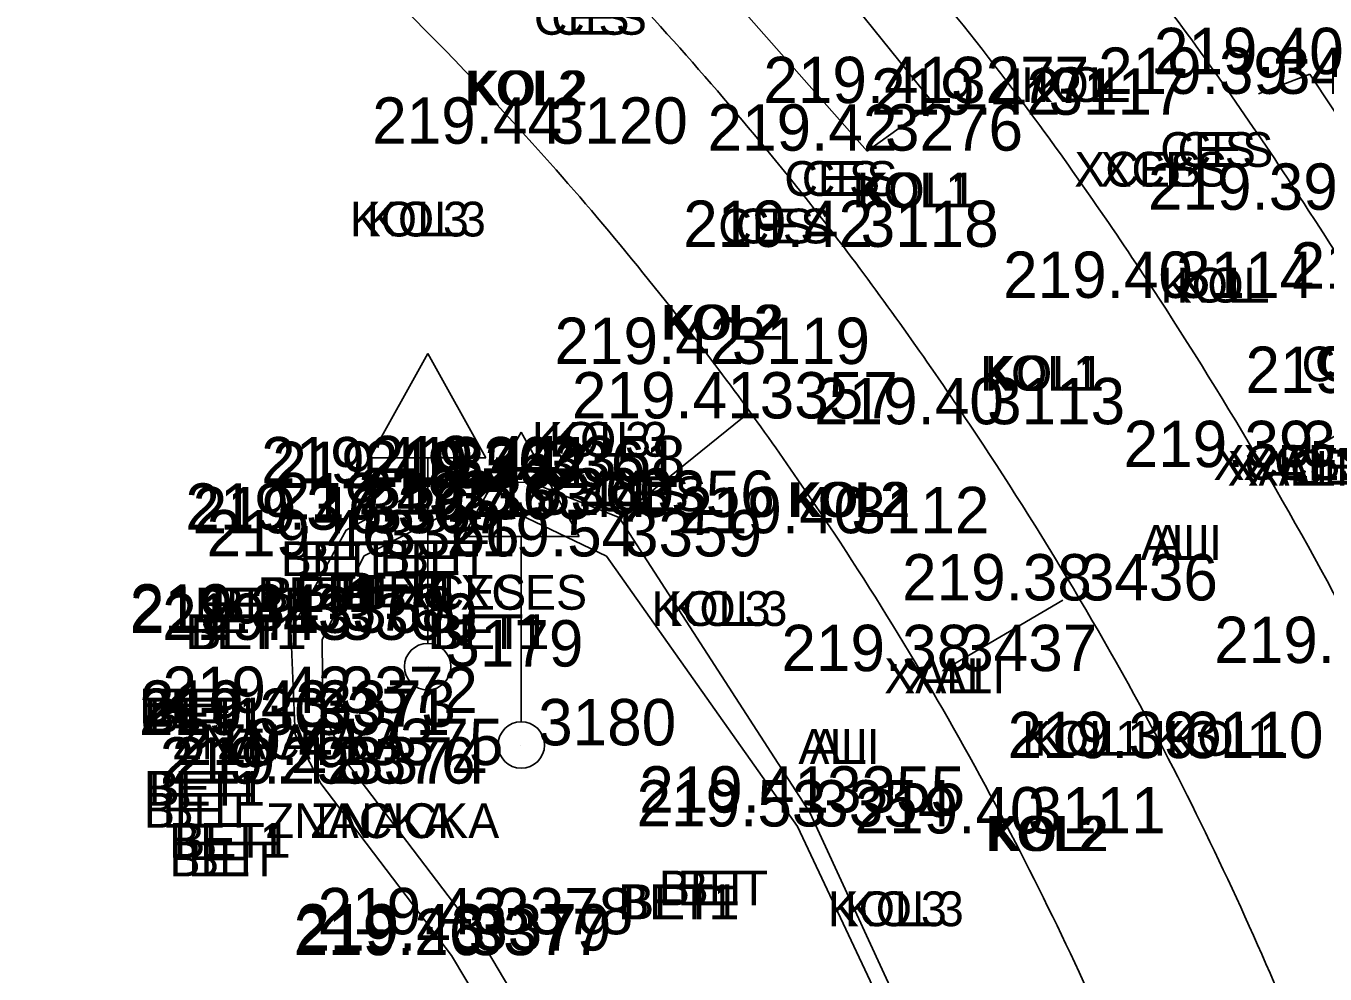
# Model space of a CAD drawing. Extents: x -471047 to -470889, y -1102859 to -1102000.
# Drawn here: x -470937.81 to -470926.61, y -1102024.77 to -1102016.59 of the extents above; entities that cross this region are included whole.
import ezdxf

# ---------------------------------------------------------------- set-up
doc = ezdxf.new("R2010")
doc.units = 0
for name, color, linetype in [('Vrstva 1', 7, 'Continuous'), ('Vrstva 19', 7, 'Continuous'), ('Vrstva 29', 7, 'Continuous'), ('Vrstva 34', 7, 'Continuous'), ('Vrstva 35', 7, 'Continuous'), ('Vrstva 36', 7, 'Continuous'), ('Vrstva 38', 7, 'Continuous'), ('Vrstva 7', 7, 'Continuous'), ('Vrstva 8', 7, 'Continuous')]:
    doc.layers.add(name, color=color, linetype=linetype)

msp = doc.modelspace()

# ---------------------------------------------------------------- linework, layer by layer
at = {"layer": 'Vrstva 1'}
for points in [[(-471040.344, -1102858.385), (-471031.676, -1102846.187), (-471026.357, -1102838.629), (-471023.212, -1102833.975), (-471019.21, -1102827.465), (-471016.861, -1102823.272), (-471013.099, -1102815.912), (-471010.824, -1102810.955), (-471007.329, -1102802.292), (-471005.34, -1102796.515), (-471002.842, -1102787.838), (-471001.3, -1102780.997), (-471000.19, -1102774.713), (-470999.247, -1102768.204), (-470998.794, -1102764.784), (-470997.199, -1102751.812), (-470994.899, -1102732.807), (-470992.551, -1102713.262), (-470990.326, -1102694.887), (-470988.122, -1102676.57), (-470985.812, -1102657.305), (-470983.537, -1102638.407), (-470981.386, -1102620.622), (-470979.843, -1102608.014), (-470976.377, -1102579.253), (-470972.945, -1102550.69), (-470970.475, -1102530.206), (-470967.905, -1102508.801), (-470965.053, -1102485.131), (-470962.734, -1102465.9), (-470960.173, -1102444.812), (-470957.795, -1102425.103), (-470954.965, -1102401.839), (-470953.834, -1102392.574), (-470952.33, -1102379.985), (-470950.744, -1102366.853), (-470948.978, -1102352.106), (-470947.037, -1102335.844), (-470944.949, -1102318.462), (-470944.013, -1102310.745), (-470942.39, -1102297.267), (-470939.519, -1102273.45), (-470937.593, -1102257.43), (-470936.064, -1102244.81), (-470934.114, -1102228.634), (-470931.621, -1102207.856), (-470929.536, -1102190.857), (-470926.572, -1102166.31), (-470924.91, -1102152.663), (-470923.413, -1102140.333), (-470921.923, -1102127.669), (-470921.155, -1102120.084), (-470920.446, -1102109.574), (-470919.912, -1102099.137), (-470919.63, -1102088.981), (-470919.523, -1102081.193), (-470919.563, -1102070.395), (-470919.714, -1102064.236), (-470920.134, -1102054.704), (-470920.462, -1102047.615), (-470920.599, -1102044.52), (-470920.743, -1102041.873), (-470921.125, -1102034.455), (-470921.774, -1102030.337), (-470922.418, -1102027.787), (-470923.734, -1102023.93), (-470924.872, -1102021.434), (-470926.752, -1102018.182), (-470927.953, -1102016.45), (-470929.616, -1102014.424), (-470932.252, -1102011.756), (-470935.111, -1102009.425), (-470938.391, -1102007.371), (-470942.651, -1102005.401)], [(-471041.328, -1102857.18), (-471032.144, -1102844.242), (-471027.583, -1102837.763), (-471024.388, -1102833.028), (-471020.451, -1102826.6), (-471018.089, -1102822.378), (-471014.542, -1102815.445), (-471012.233, -1102810.418), (-471009.247, -1102803.108), (-471006.795, -1102796.098), (-471004.315, -1102787.532), (-471002.782, -1102780.723), (-471001.674, -1102774.458), (-471000.75, -1102768.095), (-471000.28, -1102764.601), (-470998.692, -1102751.741), (-470996.378, -1102732.635), (-470994.028, -1102713.058), (-470991.808, -1102694.749), (-470989.616, -1102676.447), (-470987.284, -1102657.013), (-470985.031, -1102638.272), (-470982.87, -1102620.431), (-470981.334, -1102607.933), (-470977.881, -1102579.263), (-470974.429, -1102550.492), (-470971.964, -1102530.054), (-470969.391, -1102508.607), (-470966.54, -1102484.984), (-470964.231, -1102465.853), (-470961.679, -1102444.752), (-470959.304, -1102425.078), (-470956.455, -1102401.634), (-470955.339, -1102392.489), (-470953.812, -1102379.71), (-470952.249, -1102366.808), (-470950.479, -1102352.023), (-470948.536, -1102335.868), (-470946.426, -1102318.233), (-470945.493, -1102310.531), (-470943.864, -1102297.013), (-470940.984, -1102273.071), (-470939.078, -1102257.195), (-470937.559, -1102244.684), (-470935.592, -1102228.353), (-470933.101, -1102207.653), (-470931.011, -1102190.57), (-470928.046, -1102166.021), (-470926.409, -1102152.578), (-470924.898, -1102140.121), (-470923.427, -1102127.544), (-470922.647, -1102119.826), (-470921.919, -1102109.229), (-470921.42, -1102099.134), (-470921.127, -1102089.016), (-470921.023, -1102081.453), (-470921.061, -1102070.468), (-470921.209, -1102064.314), (-470921.666, -1102053.966), (-470922.156, -1102043.345), (-470922.299, -1102039.934), (-470922.637, -1102034.36), (-470923.091, -1102031.241), (-470923.847, -1102028.247), (-470925.083, -1102024.594), (-470926.222, -1102022.086), (-470928.04, -1102018.943), (-470929.138, -1102017.357), (-470930.929, -1102015.175), (-470933.062, -1102013.049), (-470936.379, -1102010.368), (-470939.169, -1102008.662), (-470942.899, -1102006.906), (-470945.661, -1102005.908)], [(-471043.557, -1102855.955), (-471035.129, -1102844.026), (-471029.872, -1102836.499), (-471026.577, -1102831.578), (-471022.675, -1102825.415), (-471020.123, -1102821.053), (-471016.667, -1102814.59), (-471014.208, -1102809.45), (-471011.177, -1102802.451), (-471008.55, -1102795.333), (-471006.082, -1102787.209), (-471004.464, -1102780.376), (-471003.265, -1102774.167), (-471002.327, -1102767.948), (-471001.636, -1102762.527), (-471000.297, -1102751.605), (-470997.959, -1102732.524), (-470995.602, -1102712.802), (-470993.412, -1102694.623), (-470991.21, -1102676.17), (-470988.891, -1102656.857), (-470986.625, -1102638.083), (-470984.455, -1102620.195), (-470982.936, -1102607.733), (-470979.497, -1102579.223), (-470976.023, -1102550.279), (-470973.554, -1102529.822), (-470970.991, -1102508.497), (-470968.146, -1102484.787), (-470965.835, -1102465.72), (-470963.284, -1102444.529), (-470960.91, -1102424.942), (-470958.043, -1102401.343), (-470956.946, -1102392.356), (-470955.396, -1102379.408), (-470953.851, -1102366.636), (-470952.049, -1102351.733), (-470950.124, -1102335.611), (-470948.034, -1102318.083), (-470947.094, -1102310.328), (-470945.421, -1102296.51), (-470942.58, -1102272.848), (-470940.675, -1102256.948), (-470939.176, -1102244.526), (-470937.187, -1102228.174), (-470934.708, -1102207.467), (-470932.621, -1102190.433), (-470929.634, -1102165.778), (-470928.004, -1102152.415), (-470926.45, -1102139.595), (-470925.003, -1102127.418), (-470924.249, -1102119.695), (-470923.515, -1102109.093), (-470923.018, -1102099.069), (-470922.711, -1102088.911), (-470922.643, -1102081.356), (-470922.797, -1102070.414), (-470923.018, -1102064.454), (-470923.52, -1102053.203), (-470923.823, -1102047.529), (-470924.123, -1102041.506), (-470924.462, -1102037.486), (-470924.934, -1102031.904), (-470925.664, -1102028.672), (-470926.771, -1102025.506), (-470927.959, -1102022.914), (-470929.674, -1102020.028), (-470930.76, -1102018.498), (-470932.447, -1102016.478), (-470935.215, -1102013.816), (-470937.644, -1102011.98), (-470940.381, -1102010.371), (-470943.968, -1102008.669), (-470947.145, -1102007.524), (-470950.874, -1102006.74)], [(-471044.756, -1102855.056), (-471036.376, -1102843.177), (-471031.167, -1102835.741), (-471027.859, -1102830.8), (-471023.934, -1102824.593), (-471021.43, -1102820.312), (-471018.011, -1102813.91), (-471015.536, -1102808.75), (-471012.578, -1102801.897), (-471009.95, -1102794.77), (-471007.561, -1102786.914), (-471005.936, -1102780.074), (-471004.727, -1102773.818), (-471003.828, -1102767.827), (-471003.121, -1102762.345), (-471001.787, -1102751.467), (-470999.446, -1102732.348), (-470997.073, -1102712.539), (-470994.902, -1102694.521), (-470992.696, -1102676.023), (-470990.376, -1102656.68), (-470988.131, -1102638.071), (-470985.947, -1102620.018), (-470984.417, -1102607.512), (-470980.993, -1102579.08), (-470977.514, -1102550.137), (-470975.048, -1102529.649), (-470972.488, -1102508.37), (-470969.618, -1102484.508), (-470967.34, -1102465.669), (-470964.767, -1102444.39), (-470962.402, -1102424.781), (-470959.534, -1102401.193), (-470958.432, -1102392.151), (-470956.883, -1102379.208), (-470955.335, -1102366.424), (-470953.535, -1102351.506), (-470951.606, -1102335.399), (-470949.519, -1102317.94), (-470948.575, -1102310.159), (-470946.889, -1102296.144), (-470944.056, -1102272.618), (-470942.139, -1102256.659), (-470940.657, -1102244.341), (-470938.638, -1102227.749), (-470936.19, -1102207.298), (-470934.102, -1102190.255), (-470931.124, -1102165.639), (-470929.492, -1102152.254), (-470927.915, -1102139.252), (-470926.46, -1102127.103), (-470925.74, -1102119.604), (-470925.012, -1102108.913), (-470924.523, -1102099.054), (-470924.217, -1102088.866), (-470924.148, -1102081.334), (-470924.301, -1102070.391), (-470924.518, -1102064.43), (-470924.97, -1102054.435), (-470925.588, -1102041.569), (-470925.963, -1102035.313), (-470926.405, -1102032.225), (-470927.078, -1102029.198), (-470928.123, -1102026.148), (-470929.318, -1102023.558), (-470930.84, -1102020.97), (-470931.868, -1102019.515), (-470933.443, -1102017.605), (-470936.26, -1102014.885), (-470938.429, -1102013.255), (-470941.213, -1102011.639), (-470944.847, -1102009.927), (-470947.723, -1102008.912), (-470951.444, -1102008.161), (-470954.511, -1102007.931), (-470957.895, -1102008.041)]]:
    msp.add_spline(points, degree=3, dxfattribs=at)
at = {"layer": 'Vrstva 19'}
for p, q in [((-470934.344, -1102019.421), (-470934.844, -1102020.321)), ((-470934.344, -1102019.421), (-470933.844, -1102020.321)), ((-470933.537, -1102020.097), (-470934.037, -1102020.997)), ((-470933.537, -1102020.097), (-470933.037, -1102020.997)), ((-470933.844, -1102020.321), (-470934.844, -1102020.321)), ((-470934.344, -1102020.321), (-470934.344, -1102021.921)), ((-470933.037, -1102020.997), (-470934.037, -1102020.997)), ((-470933.537, -1102020.997), (-470933.537, -1102022.597))]:
    msp.add_line(p, q, dxfattribs=at)
for centre in [(-470934.344, -1102022.121), (-470933.537, -1102022.797)]:
    msp.add_circle(centre, 0.2, dxfattribs=at)
at = {"layer": 'Vrstva 29'}
for p, q in [((-470925.914, -1102019.764), (-470926.962, -1102020.396)), ((-470928.867, -1102021.548), (-470929.907, -1102022.157))]:
    msp.add_line(p, q, dxfattribs=at)
at = {"layer": 'Vrstva 34'}
for p, q in [((-470926.74, -1102017.01), (-470926.74, -1102017.01)), ((-470927.18, -1102017.18), (-470927.18, -1102017.18)), ((-470929.98, -1102017.26), (-470929.98, -1102017.26)), ((-470929.14, -1102017.36), (-470929.14, -1102017.36)), ((-470933.44, -1102017.61), (-470933.44, -1102017.61)), ((-470930.55, -1102017.67), (-470930.55, -1102017.67)), ((-470926.75, -1102018.18), (-470926.75, -1102018.18)), ((-470930.76, -1102018.5), (-470930.76, -1102018.5)), ((-470928.04, -1102018.94), (-470928.04, -1102018.94)), ((-470931.87, -1102019.51), (-470931.87, -1102019.51)), ((-470931.63, -1102019.98), (-470931.63, -1102019.98)), ((-470929.67, -1102020.03), (-470929.67, -1102020.03)), ((-470926.96, -1102020.4), (-470926.96, -1102020.4)), ((-470934.31, -1102020.54), (-470934.31, -1102020.54)), ((-470933.46, -1102020.53), (-470933.46, -1102020.53)), ((-470934.3, -1102020.58), (-470934.3, -1102020.58)), ((-470933.51, -1102020.57), (-470933.51, -1102020.57)), ((-470934.27, -1102020.85), (-470934.27, -1102020.85)), ((-470933.56, -1102020.81), (-470933.56, -1102020.81)), ((-470932.69, -1102020.83), (-470932.69, -1102020.83)), ((-470935.05, -1102020.94), (-470935.05, -1102020.94)), ((-470935.01, -1102020.97), (-470935.01, -1102020.97)), ((-470930.84, -1102020.97), (-470930.84, -1102020.97)), ((-470934.89, -1102021.17), (-470934.89, -1102021.17)), ((-470932.8, -1102021.17), (-470932.8, -1102021.17)), ((-470928.87, -1102021.55), (-470928.87, -1102021.55)), ((-470935.53, -1102021.81), (-470935.53, -1102021.81)), ((-470935.44, -1102021.83), (-470935.44, -1102021.83)), ((-470935.25, -1102021.89), (-470935.25, -1102021.89)), ((-470934.34, -1102022.12), (-470934.34, -1102022.12)), ((-470929.91, -1102022.16), (-470929.91, -1102022.16)), ((-470935.25, -1102022.52), (-470935.25, -1102022.52)), ((-470935.44, -1102022.64), (-470935.44, -1102022.64)), ((-470935.49, -1102022.71), (-470935.49, -1102022.71)), ((-470933.54, -1102022.8), (-470933.54, -1102022.8)), ((-470935.03, -1102022.97), (-470935.03, -1102022.97)), ((-470927.96, -1102022.91), (-470927.96, -1102022.91)), ((-470935.27, -1102023.13), (-470935.27, -1102023.13)), ((-470935.17, -1102023.13), (-470935.17, -1102023.13)), ((-470931.05, -1102023.38), (-470931.05, -1102023.38)), ((-470931.16, -1102023.5), (-470931.16, -1102023.5)), ((-470929.32, -1102023.56), (-470929.32, -1102023.56)), ((-470933.91, -1102024.43), (-470933.91, -1102024.43)), ((-470934.1, -1102024.57), (-470934.1, -1102024.57)), ((-470934.14, -1102024.61), (-470934.14, -1102024.61))]:
    msp.add_line(p, q, dxfattribs=at)
at = {"layer": 'Vrstva 7'}
for p, q in [((-470934.27, -1102020.845), (-470934.891, -1102021.165)), ((-470933.557, -1102020.806), (-470934.27, -1102020.845)), ((-470932.802, -1102021.167), (-470933.557, -1102020.806)), ((-470934.891, -1102021.165), (-470935.254, -1102021.887)), ((-470931.155, -1102023.5), (-470932.802, -1102021.167)), ((-470935.254, -1102021.887), (-470935.248, -1102022.521)), ((-470935.248, -1102022.521), (-470935.026, -1102022.967)), ((-470935.026, -1102022.967), (-470933.911, -1102024.434)), ((-470929.467, -1102027.081), (-470931.155, -1102023.5)), ((-470933.911, -1102024.434), (-470932.941, -1102026.079))]:
    msp.add_line(p, q, dxfattribs=at)
at = {"layer": 'Vrstva 8'}
for p, q in [((-470929.982, -1102017.262), (-470931.287, -1102015.645)), ((-470932.142, -1102015.871), (-470930.554, -1102017.673)), ((-470927.182, -1102017.181), (-470926.738, -1102017.009)), ((-470926.738, -1102017.009), (-470925.518, -1102018.861)), ((-470930.554, -1102017.673), (-470929.982, -1102017.262)), ((-470932.694, -1102020.833), (-470931.631, -1102019.976)), ((-470934.308, -1102020.539), (-470935.046, -1102020.944)), ((-470933.459, -1102020.531), (-470934.308, -1102020.539)), ((-470932.694, -1102020.833), (-470933.459, -1102020.531)), ((-470931.049, -1102023.38), (-470932.694, -1102020.833)), ((-470935.046, -1102020.944), (-470935.525, -1102021.81)), ((-470935.525, -1102021.81), (-470935.486, -1102022.706)), ((-470935.486, -1102022.706), (-470935.266, -1102023.128)), ((-470935.266, -1102023.128), (-470934.138, -1102024.613)), ((-470929.352, -1102027.057), (-470931.049, -1102023.38)), ((-470934.138, -1102024.613), (-470933.189, -1102026.203))]:
    msp.add_line(p, q, dxfattribs=at)

# ---------------------------------------------------------------- texts
at = {"layer": 'Vrstva 35'}
for s, p in [('CES', (-470933.429, -1102016.67)), ('CES', (-470933.279, -1102016.67)), ('KOL', (-470929.225, -1102017.25)), ('KOL', (-470929.089, -1102017.25)), ('KOL2', (-470934.025, -1102017.28)), ('KOL2', (-470933.991, -1102017.28)), ('CES', (-470928.029, -1102017.81)), ('CES', (-470927.879, -1102017.81)), ('XCES', (-470928.769, -1102017.98)), ('XCES', (-470928.544, -1102017.98)), ('CES', (-470931.269, -1102018.06)), ('CES', (-470931.119, -1102018.06)), ('KOL1', (-470930.682, -1102018.16)), ('KOL1', (-470930.64, -1102018.16)), ('KOL3', (-470935.015, -1102018.41)), ('KOL3', (-470934.868, -1102018.41)), ('CES', (-470931.839, -1102018.47)), ('CES', (-470931.689, -1102018.47)), ('KOL', (-470928.025, -1102018.98)), ('KOL', (-470927.889, -1102018.98)), ('KOL2', (-470932.335, -1102019.3)), ('KOL2', (-470932.301, -1102019.3)), ('CES', (-470926.809, -1102019.66)), ('CES', (-470926.659, -1102019.66)), ('KOL1', (-470929.582, -1102019.74)), ('KOL1', (-470929.54, -1102019.74)), ('KOL3', (-470933.445, -1102020.31)), ('KOL3', (-470933.298, -1102020.31)), ('XCES1 XFIE1', (-470927.57, -1102020.51)), ('XCES1 XFIE1', (-470927.312, -1102020.51)), ('XALI', (-470927.448, -1102020.56)), ('XALI', (-470927.274, -1102020.56)), ('CES XFIE', (-470926.908, -1102020.55)), ('CES', (-470932.919, -1102020.78)), ('CES', (-470932.769, -1102020.78)), ('KOL2', (-470931.245, -1102020.83)), ('KOL2', (-470931.211, -1102020.83)), ('ALI', (-470928.198, -1102021.2)), ('ALI', (-470928.099, -1102021.2)), ('BET', (-470935.61, -1102021.34)), ('BET', (-470935.449, -1102021.34)), ('BET', (-470934.76, -1102021.33)), ('BET', (-470934.599, -1102021.33)), ('BET XCES', (-470935.479, -1102021.63)), ('BET1', (-470935.102, -1102021.61)), ('BET1', (-470935.06, -1102021.61)), ('BET XCES', (-470934.954, -1102021.63)), ('BET', (-470936.35, -1102021.74)), ('BET', (-470936.189, -1102021.74)), ('BET1', (-470935.812, -1102021.65)), ('BET1', (-470935.77, -1102021.65)), ('KOL3', (-470932.415, -1102021.77)), ('KOL3', (-470932.268, -1102021.77)), ('BET1', (-470936.432, -1102021.97)), ('BET1', (-470936.39, -1102021.97)), ('BET1', (-470934.342, -1102021.97)), ('BET1', (-470934.3, -1102021.97)), ('XALI', (-470930.408, -1102022.35)), ('XALI', (-470930.234, -1102022.35)), ('BET', (-470936.83, -1102022.61)), ('BET', (-470936.669, -1102022.61)), ('BET1', (-470936.792, -1102022.69)), ('BET1', (-470936.75, -1102022.69)), ('ZNACKA', (-470936.54, -1102022.92)), ('ZNACKA', (-470936.154, -1102022.92)), ('ALI', (-470931.148, -1102022.96)), ('ALI', (-470931.049, -1102022.96)), ('KOL1 KOL1', (-470929.22, -1102022.89)), ('KOL1 KOL1', (-470929.112, -1102022.89)), ('BET1', (-470936.792, -1102023.32)), ('BET1', (-470936.75, -1102023.32)), ('BET', (-470936.79, -1102023.51)), ('BET', (-470936.629, -1102023.51)), ('ZNACKA', (-470935.74, -1102023.6)), ('ZNACKA', (-470935.354, -1102023.6)), ('KOL2', (-470929.535, -1102023.71)), ('KOL2', (-470929.501, -1102023.71)), ('BET1', (-470936.572, -1102023.77)), ('BET1', (-470936.53, -1102023.77)), ('BET', (-470936.57, -1102023.93)), ('BET', (-470936.409, -1102023.93)), ('BET', (-470932.35, -1102024.18)), ('BET', (-470932.189, -1102024.18)), ('BET1', (-470932.702, -1102024.3)), ('BET1', (-470932.66, -1102024.3)), ('KOL3', (-470930.895, -1102024.36)), ('KOL3', (-470930.748, -1102024.36))]:
    msp.add_text(s, height=0.3, dxfattribs=at).set_placement(p)
at = {"layer": 'Vrstva 36'}
for s, p in [(' 3277', (-470929.98, -1102017.26)), (' 3410', (-470927.18, -1102017.18)), (' 3117', (-470929.14, -1102017.36)), (' 3120', (-470933.44, -1102017.61)), (' 3276', (-470930.55, -1102017.67)), (' 3118', (-470930.76, -1102018.5)), (' 3114', (-470928.04, -1102018.94)), (' 3119', (-470931.87, -1102019.51)), (' 3357', (-470931.63, -1102019.98)), (' 3113', (-470929.67, -1102020.03)), (' 3435', (-470926.96, -1102020.4)), (' 3364', (-470934.31, -1102020.54)), (' 3362', (-470934.3, -1102020.58)), (' 3361', (-470933.51, -1102020.57)), (' 3358', (-470933.46, -1102020.53)), (' 3360', (-470933.56, -1102020.81)), (' 3356', (-470932.69, -1102020.83)), (' 3365', (-470935.05, -1102020.94)), (' 3363', (-470934.27, -1102020.85)), (' 3367', (-470935.01, -1102020.97)), (' 3112', (-470930.84, -1102020.97)), (' 3366', (-470934.89, -1102021.17)), (' 3359', (-470932.8, -1102021.17)), (' 3436', (-470928.87, -1102021.55)), (' 3370', (-470935.53, -1102021.81)), (' 3368', (-470935.44, -1102021.83)), (' 3369', (-470935.25, -1102021.89)), (' 3179', (-470934.34, -1102022.12)), (' 3437', (-470929.91, -1102022.16)), (' 3372', (-470935.25, -1102022.52)), (' 3371', (-470935.49, -1102022.71)), (' 3373', (-470935.44, -1102022.64)), (' 3180', (-470933.54, -1102022.8)), (' 3375', (-470935.03, -1102022.97)), (' 3110', (-470927.96, -1102022.91)), (' 3376', (-470935.27, -1102023.13)), (' 3374', (-470935.17, -1102023.13)), (' 3355', (-470931.05, -1102023.38)), (' 3354', (-470931.16, -1102023.5)), (' 3111', (-470929.32, -1102023.56)), (' 3378', (-470933.91, -1102024.43)), (' 3377', (-470934.14, -1102024.61)), (' 3379', (-470934.1, -1102024.57))]:
    msp.add_text(s, height=0.4, dxfattribs=at).set_placement(p)
at = {"layer": 'Vrstva 38'}
for s, p in [('219.40 ', (-470928.083, -1102017.01)), ('219.41 ', (-470931.45, -1102017.26)), ('219.39 ', (-470928.564, -1102017.18)), ('219.42 ', (-470930.521, -1102017.36)), ('219.44 ', (-470934.822, -1102017.61)), ('219.42 ', (-470931.931, -1102017.67)), ('219.39 ', (-470928.134, -1102018.18)), ('219.42 ', (-470932.141, -1102018.5)), ('219.40 ', (-470929.383, -1102018.94)), ('219.39 ', (-470926.904, -1102018.86)), ('219.42 ', (-470933.251, -1102019.51)), ('219.39 ', (-470927.294, -1102019.76)), ('219.41 ', (-470933.1, -1102019.98)), ('219.40 ', (-470931.013, -1102020.03)), ('219.39 ', (-470928.344, -1102020.4)), ('219.41 ', (-470935.78, -1102020.54)), ('219.49 ', (-470935.684, -1102020.58)), ('219.53 ', (-470934.893, -1102020.57)), ('219.44 ', (-470934.842, -1102020.53)), ('219.53 ', (-470934.943, -1102020.81)), ('219.44 ', (-470934.072, -1102020.83)), ('219.37 ', (-470936.433, -1102020.94)), ('219.49 ', (-470935.654, -1102020.85)), ('219.46 ', (-470936.37, -1102020.97)), ('219.40 ', (-470932.183, -1102020.97)), ('219.46 ', (-470936.25, -1102021.17)), ('219.54 ', (-470934.182, -1102021.17)), ('219.38 ', (-470930.254, -1102021.55)), ('219.34 ', (-470936.912, -1102021.81)), ('219.41 ', (-470936.91, -1102021.83)), ('219.43 ', (-470936.633, -1102021.89)), ('219.38 ', (-470931.294, -1102022.16)), ('219.40 ', (-470927.563, -1102022.09)), ('219.42 ', (-470936.631, -1102022.52)), ('219.30 ', (-470936.833, -1102022.71)), ('219.43 ', (-470936.823, -1102022.64)), ('219.41 ', (-470936.5, -1102022.97)), ('219.39 ', (-470929.344, -1102022.91)), ('219.29 ', (-470936.654, -1102023.13)), ('219.42 ', (-470936.551, -1102023.13)), ('219.41 ', (-470932.52, -1102023.38)), ('219.53 ', (-470932.543, -1102023.5)), ('219.40 ', (-470930.663, -1102023.56)), ('219.43 ', (-470935.293, -1102024.43)), ('219.26 ', (-470935.5, -1102024.61)), ('219.43 ', (-470935.483, -1102024.57))]:
    msp.add_text(s, height=0.4, dxfattribs=at).set_placement(p)

doc.saveas('drawing.dxf')
